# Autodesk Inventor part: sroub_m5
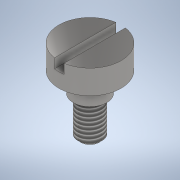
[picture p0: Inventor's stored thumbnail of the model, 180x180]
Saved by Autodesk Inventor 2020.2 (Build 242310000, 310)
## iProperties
Created: 2020-04
Part Number: sroub_m5
Material: Stainless Steel
Document SubType Name: Modeling
Designer: freem
Density: 8 g/cm^3
Appearance: Semi-Polished
Author: freem
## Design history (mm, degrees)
sketch "Sketch1"
  geometry: C1 r 6.5 at (0, 0); 1 further point
  constraints: 1 centre point, 1 coincident
  dimensions: "d0" = 13 diameter of C1
extrude "Extrusion1" new body sketch "Sketch1" distance "d1" = 5; taper "d2" = 0 deg
sketch "Sketch2"
  geometry: L1 (-1, -6.423)-(-1, 6.423); L2 (1, -6.423)-(1, 6.423); A1 r 6.5 centre (0, 0) between (-1, -6.423) and (-1, 6.423) reference; 1 further point
  constraints: 4 end point, 4 point on circle, 2 parallel, 2 vertical
  dimensions: "d3" = 2 distance between parallel lines of L1 L2
extrude "Extrusion2" cut sketch "Sketch2" distance "d4" = 2; taper "d5" = 0 deg
sketch "Sketch3"
  geometry: C1 r 3.5 at (0, 0); 1 further point
  constraints: 1 centre point, 1 coincident
  dimensions: "d6" = 7 diameter of C1
extrude "Extrusion3" join sketch "Sketch3" distance "d7" = 4.1; taper "d8" = 0 deg
sketch "Sketch4"
  geometry: C1 r 2.5 at (0, 0); 1 further point
  constraints: 1 centre point, 1 coincident
  dimensions: "d9" = 5 diameter of C1
extrude "Extrusion4" join sketch "Sketch4" distance "d10" = 8; taper "d11" = 0 deg
chamfer "Chamfer1" distance "d12" = 0.6; stored, may be unused: second distance "d13" = 2, angle "d14" = 45 deg
thread "Thread1" dims "d15" = 7.4, "d16" = 0
body "Solid1"
